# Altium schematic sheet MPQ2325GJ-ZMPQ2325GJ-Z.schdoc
size 127 x 101 mm
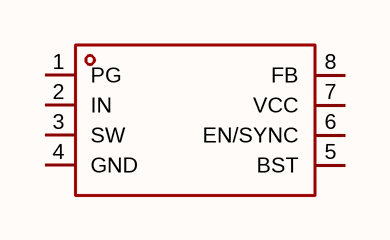
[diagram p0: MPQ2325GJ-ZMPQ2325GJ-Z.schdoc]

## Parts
U?  mpq2325gj-z  [TSOT-23-8_L2.9-W1.6-P0.65-LS2.8-BL-1]  (value not drawn)

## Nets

Not connected (* = marked no-connect by the designer): U? 1(PG) 2(IN) 3(SW) 4(GND) 5(BST) 6(EN/SYNC) 7(VCC) 8(FB)

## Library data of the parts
U? = mpq2325gj-z: 功能类型:降压型;工作电压:4.5V~24V;输出电压:-;输出电流:3A;输出类型:可调;; Manufacturer: MPS(芯源); AddInBom: yes; ModelId: bc3032edd337434b8e579663e61a6d1f; ModelTransform: 114.317,110.236,0,0,0,0,-0.005,0,0; Function: 降压型; Output Current: 3A; Frequency - Switching: 500kHz; Synchronous Rectifier: 是; Number of Outputs: 1; Topology: 降压式; Quiescent Current: 180uA; Switch tube (built-in/external): 内置; Output Type: 可调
